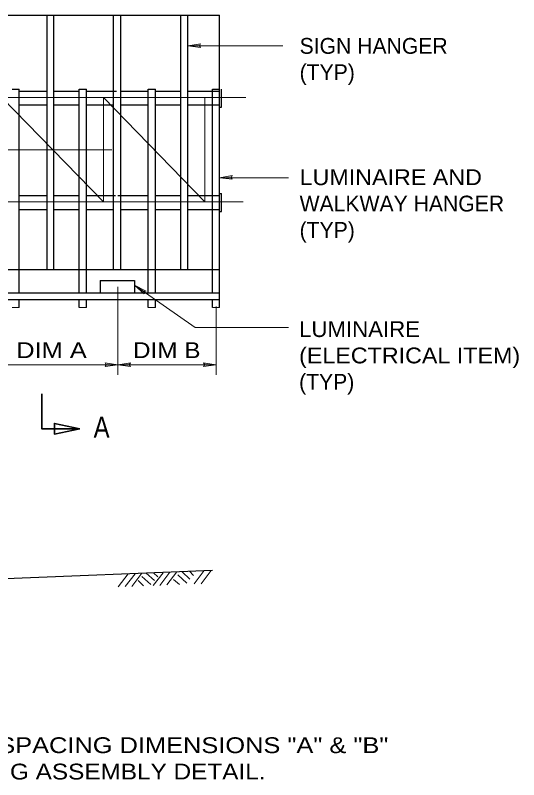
# Model space of a CAD drawing. Extents: x 312601.858 to 312602.699, y 144420.109 to 144420.704.
# Drawn here: x 312602.0584 to 312602.1539, y 144420.4634 to 144420.6083 of the extents above; entities that cross this region are included whole.
import ezdxf
from ezdxf.enums import TextEntityAlignment as Align

# ---------------------------------------------------------------- set-up
doc = ezdxf.new("R2010")
doc.units = 0
doc.header["$LTSCALE"] = 0.0012
for name, pattern in [('DOT_DASHED', [7.7, 5, -1.2, 0.3, -1.2]), ('LONG_DASH_SHORT_DASH', [9.9, 6, -1.2, 1.5, -1.2]), ('LONG_DASHED', [7.5, 6, -1.5])]:
    doc.linetypes.add(name, pattern=pattern)
for name, color, linetype, lineweight in [('1', 7, 'Continuous', 25), ('2', 7, 'Continuous', 25), ('39', 7, 'Continuous', 13)]:
    doc.layers.add(name, color=color, linetype=linetype, lineweight=lineweight)

msp = doc.modelspace()

# ---------------------------------------------------------------- hatches: boundary and pattern name
at = {"layer": '39'}
for points in [[(312602.0933, 144420.6025), (312602.0935, 144420.6022), (312602.0911, 144420.6025), (312602.0935, 144420.6029)], [(312602.0993, 144420.5775), (312602.0995, 144420.5772), (312602.0971, 144420.5775), (312602.0995, 144420.5779)], [(312602.0828, 144420.5559), (312602.0828, 144420.5555), (312602.081, 144420.5571), (312602.0832, 144420.556)], [(312602.0756, 144420.542), (312602.0754, 144420.5424), (312602.0778, 144420.542), (312602.0754, 144420.5417)], [(312602.08, 144420.542), (312602.0802, 144420.5417), (312602.0778, 144420.542), (312602.0802, 144420.5424)], [(312602.0943, 144420.542), (312602.0941, 144420.5424), (312602.0965, 144420.542), (312602.0941, 144420.5417)]]:
    msp.add_hatch(color=256, dxfattribs=at).paths.add_polyline_path(points)

# ---------------------------------------------------------------- linework, layer by layer
at = {"layer": '1', "linetype": 'DOT_DASHED', "lineweight": 13}
msp.add_line((312601.9767, 144420.5828), (312602.1035, 144420.5828), dxfattribs=at)
at = {"layer": '1'}
for p, q in [((312602.0071, 144420.5601), (312602.0971, 144420.5601)), ((312601.993, 144420.5557), (312602.0971, 144420.5557)), ((312601.993, 144420.5544), (312602.0971, 144420.5544)), ((312602.0096, 144420.4996), (312602.0958, 144420.5031))]:
    msp.add_line(p, q, dxfattribs=at)
at = {"layer": '1', "lineweight": 13}
for p, q in [((312602.0578, 144420.5529), (312602.0591, 144420.5529)), ((312602.0705, 144420.5529), (312602.0719, 144420.5529)), ((312602.0836, 144420.5529), (312602.085, 144420.5529)), ((312602.0958, 144420.5529), (312602.0971, 144420.5529)), ((312602.0965, 144420.5531), (312602.0965, 144420.5437)), ((312602.0965, 144420.5531), (312602.0965, 144420.5499)), ((312602.0965, 144420.5481), (312602.0965, 144420.5401))]:
    msp.add_line(p, q, dxfattribs=at)
msp.add_lwpolyline([(312602.0077, 144420.542), (312602.0266, 144420.542), (312602.052, 144420.542), (312602.0778, 144420.542), (312602.0965, 144420.542)], dxfattribs=at)
at = {"layer": '2'}
for p, q in [((312602.0071, 144420.6083), (312602.0971, 144420.6083)), ((312602.0971, 144420.5529), (312602.0971, 144420.6083)), ((312602.0578, 144420.5943), (312602.0591, 144420.5943)), ((312602.0705, 144420.5943), (312602.0719, 144420.5943)), ((312602.0836, 144420.5943), (312602.085, 144420.5943)), ((312602.0958, 144420.5943), (312602.0971, 144420.5943)), ((312602.0971, 144420.5909), (312602.0975, 144420.5909)), ((312602.0971, 144420.5745), (312602.0975, 144420.5745)), ((312602.0975, 144420.5711), (312602.0975, 144420.5745)), ((312602.0971, 144420.5711), (312602.0975, 144420.5711)), ((312602.0591, 144420.5557), (312602.0591, 144420.5601)), ((312602.0705, 144420.5557), (312602.0705, 144420.5601)), ((312602.0719, 144420.5557), (312602.0719, 144420.5601)), ((312602.0836, 144420.5557), (312602.0836, 144420.5601)), ((312602.085, 144420.5557), (312602.085, 144420.5601)), ((312602.0958, 144420.5557), (312602.0958, 144420.5601)), ((312602.0745, 144420.558), (312602.081, 144420.558)), ((312602.0745, 144420.558), (312602.0745, 144420.5557)), ((312602.081, 144420.558), (312602.081, 144420.5557)), ((312602.0591, 144420.5529), (312602.0591, 144420.5544)), ((312602.0705, 144420.5529), (312602.0705, 144420.5544)), ((312602.0719, 144420.5529), (312602.0719, 144420.5544)), ((312602.0836, 144420.5529), (312602.0836, 144420.5544)), ((312602.085, 144420.5529), (312602.085, 144420.5544)), ((312602.0958, 144420.5529), (312602.0958, 144420.5544))]:
    msp.add_line(p, q, dxfattribs=at)
at = {"layer": '2', "linetype": 'LONG_DASHED'}
for p, q in [((312602.0644, 144420.5601), (312602.0644, 144420.6083)), ((312602.0657, 144420.5601), (312602.0657, 144420.6083)), ((312602.077, 144420.5601), (312602.077, 144420.6083)), ((312602.0784, 144420.5601), (312602.0784, 144420.6083)), ((312602.0898, 144420.5601), (312602.0898, 144420.6083)), ((312602.0911, 144420.5601), (312602.0911, 144420.6083)), ((312602.0591, 144420.5601), (312602.0591, 144420.5943)), ((312602.0591, 144420.5939), (312602.0644, 144420.5939)), ((312602.0657, 144420.5939), (312602.0705, 144420.5939)), ((312602.0705, 144420.5601), (312602.0705, 144420.5943)), ((312602.0719, 144420.5601), (312602.0719, 144420.5943)), ((312602.0719, 144420.5939), (312602.0776, 144420.5939)), ((312602.0784, 144420.5939), (312602.0836, 144420.5939)), ((312602.0836, 144420.5601), (312602.0836, 144420.5943)), ((312602.085, 144420.5601), (312602.085, 144420.5943)), ((312602.085, 144420.5939), (312602.0898, 144420.5939)), ((312602.0911, 144420.5939), (312602.0971, 144420.5939)), ((312602.0958, 144420.5601), (312602.0958, 144420.5943)), ((312602.0591, 144420.5913), (312602.0644, 144420.5913)), ((312602.0657, 144420.5913), (312602.0705, 144420.5913)), ((312602.0719, 144420.5913), (312602.077, 144420.5913)), ((312602.0784, 144420.5913), (312602.0836, 144420.5913)), ((312602.085, 144420.5913), (312602.0898, 144420.5913)), ((312602.0911, 144420.5913), (312602.0971, 144420.5913)), ((312602.0591, 144420.5741), (312602.0644, 144420.5741)), ((312602.0657, 144420.5741), (312602.0705, 144420.5741)), ((312602.0719, 144420.5741), (312602.0774, 144420.5741)), ((312602.0778, 144420.5741), (312602.0836, 144420.5741)), ((312602.085, 144420.5741), (312602.0898, 144420.5741)), ((312602.0911, 144420.5741), (312602.0971, 144420.5741)), ((312602.0591, 144420.5715), (312602.0644, 144420.5715)), ((312602.0657, 144420.5715), (312602.0705, 144420.5715)), ((312602.0719, 144420.5715), (312602.077, 144420.5715)), ((312602.0784, 144420.5715), (312602.0836, 144420.5715)), ((312602.085, 144420.5715), (312602.0898, 144420.5715)), ((312602.0911, 144420.5715), (312602.0971, 144420.5715))]:
    msp.add_line(p, q, dxfattribs=at)
at = {"layer": '2', "lineweight": 13}
for p, q in [((312602.0911, 144420.6025), (312602.1091, 144420.6025)), ((312602.0971, 144420.5775), (312602.1102, 144420.5775)), ((312602.0778, 144420.5568), (312602.0778, 144420.5401)), ((312602.0778, 144420.5023), (312602.095, 144420.503)), ((312602.0779, 144420.4999), (312602.0798, 144420.5024)), ((312602.0792, 144420.5), (312602.0811, 144420.5024)), ((312602.0805, 144420.5), (312602.0824, 144420.5025)), ((312602.0824, 144420.5019), (312602.0841, 144420.5004)), ((312602.0832, 144420.5025), (312602.0848, 144420.5011)), ((312602.0845, 144420.5002), (312602.0864, 144420.5026)), ((312602.0846, 144420.5026), (312602.0854, 144420.5018)), ((312602.0858, 144420.5002), (312602.0877, 144420.5027)), ((312602.0871, 144420.5003), (312602.089, 144420.5028)), ((312602.0892, 144420.5022), (312602.0909, 144420.5006)), ((312602.09, 144420.5028), (312602.0915, 144420.5014)), ((312602.0914, 144420.5029), (312602.0922, 144420.5021)), ((312602.0923, 144420.5005), (312602.0942, 144420.503)), ((312602.0936, 144420.5005), (312602.0955, 144420.503)), ((312602.0817, 144420.5011), (312602.0827, 144420.5001)), ((312602.0884, 144420.5013), (312602.0895, 144420.5004))]:
    msp.add_line(p, q, dxfattribs=at)
at = {"layer": '2', "linetype": 'LONG_DASH_SHORT_DASH', "lineweight": 13}
for p, q in [((312602.0784, 144420.5962), (312602.0784, 144420.5764)), ((312602.0132, 144420.5927), (312602.1021, 144420.5927)), ((312602.0751, 144420.5927), (312602.0751, 144420.5729))]:
    msp.add_line(p, q, dxfattribs=at)
at = {"layer": '2'}
msp.add_lwpolyline([(312602.0975, 144420.5909), (312602.0975, 144420.5943), (312602.0975, 144420.5943)], dxfattribs=at)
at = {"layer": '2', "linetype": 'LONG_DASH_SHORT_DASH', "lineweight": 13}
for points in [[(312602.0364, 144420.5927), (312602.0558, 144420.5729), (312602.0751, 144420.5729)], [(312602.0558, 144420.5927), (312602.0751, 144420.5729), (312602.1016, 144420.5729)], [(312602.0751, 144420.5927), (312602.0943, 144420.5729), (312602.0943, 144420.5927)]]:
    msp.add_lwpolyline(points, dxfattribs=at)
at = {"layer": '2', "lineweight": 13}
msp.add_lwpolyline([(312602.081, 144420.5571), (312602.0925, 144420.5491), (312602.1102, 144420.5491)], dxfattribs=at)
at = {"layer": '39'}
for points in [[(312602.0933, 144420.6025), (312602.0935, 144420.6022), (312602.0911, 144420.6025), (312602.0935, 144420.6029)], [(312602.0993, 144420.5775), (312602.0995, 144420.5772), (312602.0971, 144420.5775), (312602.0995, 144420.5779)], [(312602.0828, 144420.5559), (312602.0828, 144420.5555), (312602.081, 144420.5571), (312602.0832, 144420.556)], [(312602.0756, 144420.542), (312602.0754, 144420.5424), (312602.0778, 144420.542), (312602.0754, 144420.5417)], [(312602.08, 144420.542), (312602.0802, 144420.5417), (312602.0778, 144420.542), (312602.0802, 144420.5424)], [(312602.0943, 144420.542), (312602.0941, 144420.5424), (312602.0965, 144420.542), (312602.0941, 144420.5417)], [(312602.0658, 144420.5309), (312602.0706, 144420.5299), (312602.0658, 144420.5289)]]:
    msp.add_lwpolyline(points, close=True, dxfattribs=at)
at = {"layer": '39', "lineweight": 35}
msp.add_lwpolyline([(312602.0704, 144420.5299), (312602.0634, 144420.5299), (312602.0634, 144420.5365)], dxfattribs=at)
msp.add_lwpolyline([(312602.0706, 144420.5299), (312602.0658, 144420.5289), (312602.0658, 144420.5309)], close=True, dxfattribs=at)

# ---------------------------------------------------------------- texts
at = {"layer": '1'}
for s, width, p in [('LUMINAIRE', 1.05, (312602.1122, 144420.5473)), ('(ELECTRICAL ITEM)', 1.1, (312602.1122, 144420.5423)), ('FOR LUMINAIRE SPACING DIMENSIONS "A" & "B"', 1.2, (312602.0161, 144420.4684)), ('SEE SIGN LIGHTING ASSEMBLY DETAIL.', 1.15, (312602.0161, 144420.4634))]:
    msp.add_text(s, height=0.003, dxfattribs=dict(at, width=width)).set_placement(p)
for s, height, width, p in [('DIM A', 0.003, 1.2, (312602.06525, 144420.5433)), ('DIM B', 0.003, 1.15, (312602.0871, 144420.5433)), ('A', 0.004, 0.85, (312602.07475, 144420.5282))]:
    msp.add_text(s, height=height, dxfattribs=dict(at, width=width)).set_placement(p, align=Align.CENTER)
msp.add_text('(TYP)', height=0.003, dxfattribs=at).set_placement((312602.1122, 144420.5373))
at = {"layer": '2'}
for s, p in [('SIGN HANGER', (312602.1123, 144420.601)), ('(TYP)', (312602.1123, 144420.596)), ('WALKWAY HANGER', (312602.1123, 144420.5711)), ('(TYP)', (312602.1123, 144420.5661))]:
    msp.add_text(s, height=0.003, dxfattribs=at).set_placement(p)
at = {"layer": '2', "width": 1.1}
msp.add_text('LUMINAIRE AND', height=0.003, dxfattribs=at).set_placement((312602.1123, 144420.5761))

doc.saveas('drawing.dxf')
